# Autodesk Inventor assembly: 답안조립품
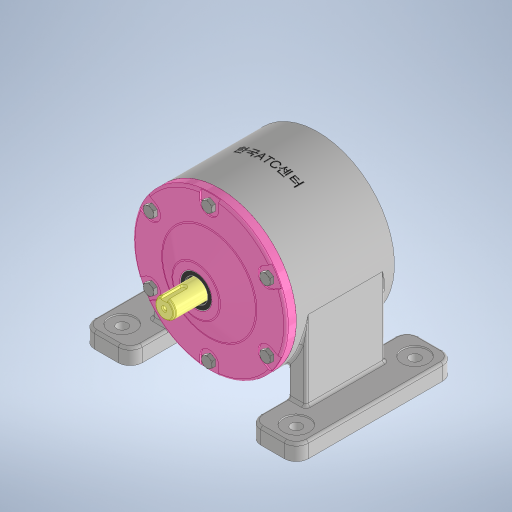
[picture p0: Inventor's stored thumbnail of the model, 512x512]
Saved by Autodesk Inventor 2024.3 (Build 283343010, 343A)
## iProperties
Created: 2025-12
Part Number: 답안조립품
Document SubType Name: Assembly
Designer: PC2-15
Author: PC2-15
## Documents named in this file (17)
- C:\Users\PC2-15\Desktop\751203V1009\답안조립품.iam
- C:\Users\PC2-15\Desktop\751203V1009\본체.ipt
- C:\Users\PC2-15\Desktop\751203V1009\깊은 홈 볼 베어링 6004.ipt
- C:\Users\PC2-15\Desktop\751203V1009\기어 축.ipt
- C:\Users\PC2-15\Desktop\751203V1009\칼라 1.ipt
- C:\Users\PC2-15\Desktop\751203V1009\평행 키 6x6x16.ipt
- C:\Users\PC2-15\Desktop\751203V1009\구동 기어.ipt
- C:\Users\PC2-15\Desktop\751203V1009\엔드 캡.ipt
- C:\Users\PC2-15\Desktop\751203V1009\6각 구멍붙이 볼트 M4x10.ipt
- C:\Users\PC2-15\Desktop\751203V1009\출력 축.ipt
- C:\Users\PC2-15\Desktop\751203V1009\칼라 2.ipt
- C:\Users\PC2-15\Desktop\751203V1009\종동 기어.ipt
- C:\Users\PC2-15\Desktop\751203V1009\깊은 홈 볼 베어링 6005.ipt
- C:\Users\PC2-15\Desktop\751203V1009\C형 멈춤링 구멍용 42.ipt
- C:\Users\PC2-15\Desktop\751203V1009\커버.ipt
- C:\Users\PC2-15\Desktop\751203V1009\오일 실 25 40 8.ipt
- C:\Users\PC2-15\Desktop\751203V1009\6각 머리 볼트 M8x20.ipt
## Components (9 placed, 4 different names)
1. 구동 기어:1
2. C형 멈춤링 구멍용 42:1
3. 6각 구멍붙이 볼트 M4x10:1
4. 6각 머리 볼트 M8x20:1
5. 6각 머리 볼트 M8x20:2
6. 6각 머리 볼트 M8x20:3
7. 6각 머리 볼트 M8x20:4
8. 6각 머리 볼트 M8x20:5
9. 6각 머리 볼트 M8x20:6
